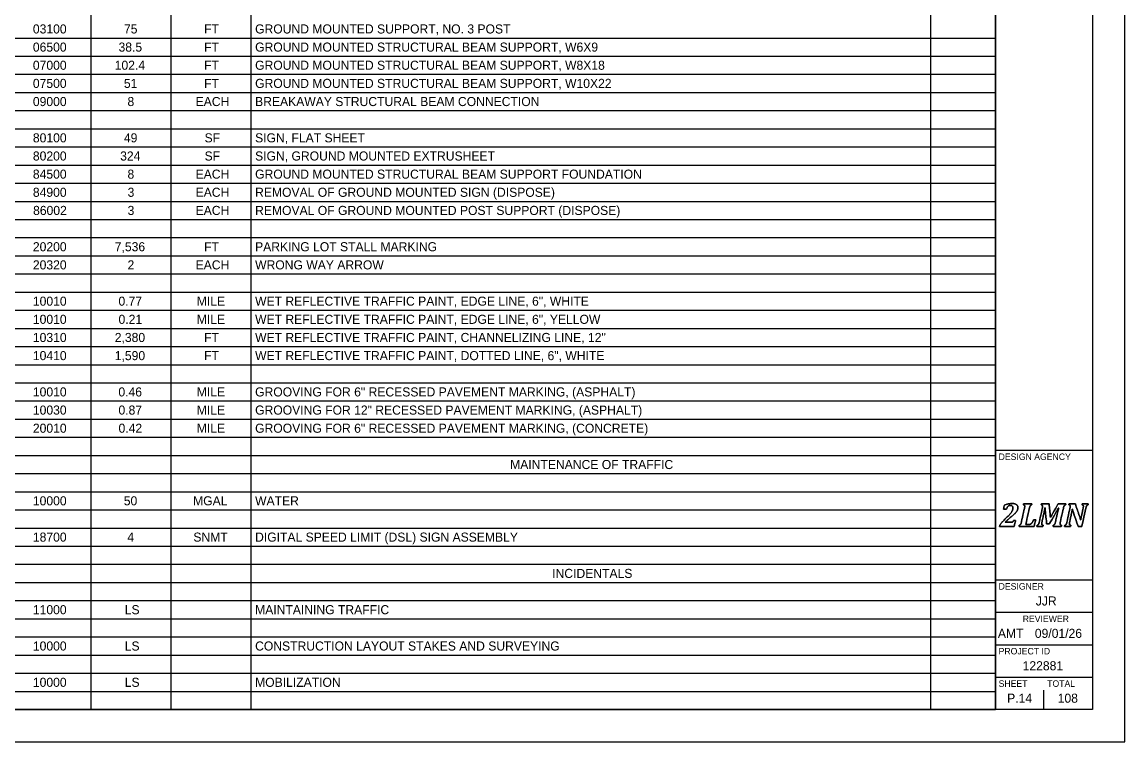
# Model space of a CAD drawing. Extents: x 0 to 34, y 0 to 22.
# Drawn here: x 16.98 to 34, y 0 to 11.11 of the extents above; entities that cross this region are included whole.
import ezdxf

# ---------------------------------------------------------------- set-up
doc = ezdxf.new("R2010")
doc.units = 0
for name, color, linetype in [('SH_Border', 7, 'Continuous'), ('SH_Cut_Line', 7, 'Continuous'), ('SH_Data', 7, 'Continuous'), ('SH_Text', 7, 'Continuous')]:
    doc.layers.add(name, color=color, linetype=linetype)

msp = doc.modelspace()

# ---------------------------------------------------------------- linework, layer by layer
at = {"layer": 'SH_Border'}
for p, q in [((32, 0.5), (32, 21.5)), ((32, 4.5), (33.5, 4.5)), ((32, 2.5), (33.5, 2.5)), ((32, 2), (33.5, 2)), ((32, 1.5), (33.5, 1.5)), ((32, 1), (33.5, 1))]:
    msp.add_line(p, q, dxfattribs=at)
msp.add_lwpolyline([(1.5, 21.5), (33.5, 21.5), (33.5, 0.5), (1.5, 0.5)], close=True, dxfattribs=at)
at = {"layer": 'SH_Cut_Line'}
msp.add_lwpolyline([(0, 0), (34, 0), (34, 22), (0, 22)], close=True, dxfattribs=at)
at = {"layer": 'SH_Data'}
for p, q in [((32.75, 3.5), (32.75, 3.5)), ((32.75, 0.5), (32.75, 0.8)), ((32.375, 0.675), (32.375, 0.675))]:
    msp.add_line(p, q, dxfattribs=at)
for points in [[(32.237, 3.388), (32.246, 3.388), (32.253, 3.389), (32.258, 3.39), (32.263, 3.392), (32.267, 3.394), (32.27, 3.397), (32.273, 3.401), (32.277, 3.408), (32.281, 3.417), (32.281, 3.417), (32.312, 3.417), (32.312, 3.417), (32.312, 3.417), (32.29, 3.326), (32.29, 3.326), (32.29, 3.326), (32.066, 3.326), (32.066, 3.326), (32.066, 3.326), (32.069, 3.343), (32.069, 3.343), (32.078, 3.358), (32.091, 3.375), (32.106, 3.394), (32.122, 3.412), (32.144, 3.435), (32.172, 3.462), (32.197, 3.486), (32.217, 3.506), (32.23, 3.521), (32.243, 3.537), (32.253, 3.551), (32.259, 3.566), (32.266, 3.58), (32.269, 3.595), (32.269, 3.61), (32.269, 3.622), (32.266, 3.632), (32.26, 3.64), (32.253, 3.647), (32.245, 3.65), (32.234, 3.65), (32.22, 3.65), (32.208, 3.646), (32.198, 3.636), (32.188, 3.627), (32.18, 3.613), (32.172, 3.593), (32.172, 3.593), (32.126, 3.593), (32.126, 3.593), (32.126, 3.593), (32.14, 3.654), (32.14, 3.654), (32.166, 3.663), (32.188, 3.669), (32.205, 3.673), (32.223, 3.676), (32.24, 3.678), (32.258, 3.678), (32.278, 3.678), (32.295, 3.675), (32.309, 3.669), (32.322, 3.664), (32.332, 3.656), (32.339, 3.646), (32.345, 3.637), (32.348, 3.626), (32.348, 3.613), (32.348, 3.602), (32.346, 3.591), (32.342, 3.581), (32.339, 3.571), (32.333, 3.56), (32.324, 3.549), (32.315, 3.539), (32.304, 3.526), (32.289, 3.513), (32.275, 3.499), (32.254, 3.482), (32.228, 3.46), (32.216, 3.45), (32.202, 3.438), (32.188, 3.425), (32.174, 3.412), (32.162, 3.4), (32.154, 3.391), (32.154, 3.391), (32.153, 3.388), (32.153, 3.388), (32.153, 3.388), (32.237, 3.388), (32.237, 3.388)], [(32.237, 3.388), (32.237, 3.388), (32.153, 3.388), (32.153, 3.388), (32.153, 3.388), (32.154, 3.391), (32.154, 3.391), (32.162, 3.4), (32.174, 3.412), (32.188, 3.425), (32.202, 3.438), (32.216, 3.45), (32.228, 3.46), (32.254, 3.482), (32.275, 3.499), (32.289, 3.513), (32.304, 3.526), (32.315, 3.539), (32.324, 3.549), (32.333, 3.56), (32.339, 3.571), (32.342, 3.581), (32.346, 3.591), (32.348, 3.602), (32.348, 3.613), (32.348, 3.626), (32.345, 3.637), (32.339, 3.646), (32.332, 3.656), (32.322, 3.664), (32.309, 3.669), (32.295, 3.675), (32.278, 3.678), (32.258, 3.678), (32.24, 3.678), (32.223, 3.676), (32.205, 3.673), (32.188, 3.669), (32.166, 3.663), (32.14, 3.654), (32.14, 3.654), (32.126, 3.593), (32.126, 3.593), (32.126, 3.593), (32.172, 3.593), (32.172, 3.593), (32.18, 3.613), (32.188, 3.627), (32.198, 3.636), (32.208, 3.646), (32.22, 3.65), (32.234, 3.65), (32.245, 3.65), (32.253, 3.647), (32.26, 3.64), (32.266, 3.632), (32.269, 3.622), (32.269, 3.61), (32.269, 3.595), (32.266, 3.58), (32.259, 3.566), (32.253, 3.551), (32.243, 3.537), (32.23, 3.521), (32.217, 3.506), (32.197, 3.486), (32.172, 3.462), (32.144, 3.435), (32.122, 3.412), (32.106, 3.394), (32.091, 3.375), (32.078, 3.358), (32.069, 3.343), (32.069, 3.343), (32.066, 3.326), (32.066, 3.326), (32.066, 3.326), (32.29, 3.326), (32.29, 3.326), (32.29, 3.326), (32.312, 3.417), (32.312, 3.417), (32.312, 3.417), (32.281, 3.417), (32.281, 3.417), (32.277, 3.408), (32.273, 3.401), (32.27, 3.397), (32.267, 3.394), (32.263, 3.392), (32.258, 3.39), (32.253, 3.389), (32.246, 3.388), (32.237, 3.388)], [(32.518, 3.356), (32.527, 3.356), (32.533, 3.357), (32.538, 3.358), (32.542, 3.36), (32.546, 3.362), (32.55, 3.365), (32.554, 3.368), (32.558, 3.372), (32.562, 3.377), (32.567, 3.382), (32.571, 3.388), (32.576, 3.397), (32.58, 3.405), (32.585, 3.415), (32.589, 3.427), (32.589, 3.427), (32.624, 3.427), (32.624, 3.427), (32.624, 3.427), (32.598, 3.326), (32.598, 3.326), (32.598, 3.326), (32.365, 3.326), (32.365, 3.326), (32.365, 3.326), (32.369, 3.343), (32.369, 3.343), (32.376, 3.345), (32.381, 3.348), (32.385, 3.351), (32.389, 3.355), (32.392, 3.36), (32.395, 3.366), (32.398, 3.373), (32.4, 3.382), (32.403, 3.395), (32.403, 3.395), (32.449, 3.605), (32.449, 3.605), (32.452, 3.615), (32.453, 3.625), (32.453, 3.635), (32.453, 3.642), (32.451, 3.647), (32.448, 3.651), (32.444, 3.654), (32.439, 3.656), (32.432, 3.657), (32.432, 3.657), (32.435, 3.674), (32.435, 3.674), (32.435, 3.674), (32.563, 3.674), (32.563, 3.674), (32.563, 3.674), (32.559, 3.657), (32.559, 3.657), (32.552, 3.655), (32.547, 3.652), (32.543, 3.649), (32.539, 3.645), (32.536, 3.64), (32.533, 3.634), (32.531, 3.627), (32.528, 3.618), (32.525, 3.605), (32.525, 3.605), (32.47, 3.356), (32.47, 3.356), (32.47, 3.356), (32.518, 3.356), (32.518, 3.356)], [(32.518, 3.356), (32.518, 3.356), (32.47, 3.356), (32.47, 3.356), (32.47, 3.356), (32.525, 3.605), (32.525, 3.605), (32.528, 3.618), (32.531, 3.627), (32.533, 3.634), (32.536, 3.64), (32.539, 3.645), (32.543, 3.649), (32.547, 3.652), (32.552, 3.655), (32.559, 3.657), (32.559, 3.657), (32.563, 3.674), (32.563, 3.674), (32.563, 3.674), (32.435, 3.674), (32.435, 3.674), (32.435, 3.674), (32.432, 3.657), (32.432, 3.657), (32.439, 3.656), (32.444, 3.654), (32.448, 3.651), (32.451, 3.647), (32.453, 3.642), (32.453, 3.635), (32.453, 3.625), (32.452, 3.615), (32.449, 3.605), (32.449, 3.605), (32.403, 3.395), (32.403, 3.395), (32.4, 3.382), (32.398, 3.373), (32.395, 3.366), (32.392, 3.36), (32.389, 3.355), (32.385, 3.351), (32.381, 3.348), (32.376, 3.345), (32.369, 3.343), (32.369, 3.343), (32.365, 3.326), (32.365, 3.326), (32.365, 3.326), (32.598, 3.326), (32.598, 3.326), (32.598, 3.326), (32.624, 3.427), (32.624, 3.427), (32.624, 3.427), (32.589, 3.427), (32.589, 3.427), (32.585, 3.415), (32.58, 3.405), (32.576, 3.397), (32.571, 3.388), (32.567, 3.382), (32.562, 3.377), (32.558, 3.372), (32.554, 3.368), (32.55, 3.365), (32.546, 3.362), (32.542, 3.36), (32.538, 3.358), (32.533, 3.357), (32.527, 3.356), (32.518, 3.356)], [(32.829, 3.674), (32.829, 3.674), (32.849, 3.461), (32.849, 3.461), (32.849, 3.461), (32.969, 3.674), (32.969, 3.674), (32.969, 3.674), (33.087, 3.674), (33.087, 3.674), (33.087, 3.674), (33.084, 3.657), (33.084, 3.657), (33.077, 3.655), (33.071, 3.652), (33.067, 3.649), (33.064, 3.645), (33.06, 3.64), (33.058, 3.634), (33.055, 3.627), (33.052, 3.618), (33.05, 3.605), (33.05, 3.605), (33.003, 3.395), (33.003, 3.395), (33.002, 3.39), (33.002, 3.387), (33.001, 3.384), (33.001, 3.382), (33.001, 3.379), (33, 3.376), (33, 3.373), (33, 3.369), (33, 3.365), (33, 3.358), (33.002, 3.353), (33.005, 3.349), (33.008, 3.346), (33.014, 3.344), (33.021, 3.343), (33.021, 3.343), (33.018, 3.326), (33.018, 3.326), (33.018, 3.326), (32.89, 3.326), (32.89, 3.326), (32.89, 3.326), (32.893, 3.343), (32.893, 3.343), (32.9, 3.345), (32.906, 3.348), (32.91, 3.351), (32.914, 3.355), (32.917, 3.36), (32.919, 3.366), (32.922, 3.373), (32.925, 3.382), (32.928, 3.395), (32.928, 3.395), (32.951, 3.502), (32.951, 3.502), (32.954, 3.513), (32.957, 3.529), (32.962, 3.548), (32.967, 3.568), (32.972, 3.588), (32.978, 3.609), (32.978, 3.609), (32.973, 3.609), (32.973, 3.609), (32.965, 3.594), (32.957, 3.579), (32.948, 3.563), (32.948, 3.563), (32.833, 3.364), (32.833, 3.364), (32.833, 3.364), (32.792, 3.364), (32.792, 3.364), (32.792, 3.364), (32.775, 3.518), (32.775, 3.518), (32.773, 3.537), (32.772, 3.554), (32.77, 3.569), (32.769, 3.583), (32.768, 3.597), (32.768, 3.611), (32.768, 3.611), (32.764, 3.611), (32.764, 3.611), (32.761, 3.596), (32.758, 3.578), (32.755, 3.558), (32.751, 3.538), (32.747, 3.521), (32.744, 3.507), (32.744, 3.507), (32.72, 3.395), (32.72, 3.395), (32.719, 3.39), (32.718, 3.387), (32.718, 3.384), (32.717, 3.382), (32.717, 3.379), (32.717, 3.376), (32.717, 3.373), (32.716, 3.369), (32.716, 3.365), (32.716, 3.358), (32.718, 3.353), (32.721, 3.349), (32.725, 3.346), (32.73, 3.344), (32.738, 3.343), (32.738, 3.343), (32.734, 3.326), (32.734, 3.326), (32.734, 3.326), (32.641, 3.326), (32.641, 3.326), (32.641, 3.326), (32.644, 3.343), (32.644, 3.343), (32.651, 3.345), (32.657, 3.348), (32.661, 3.351), (32.665, 3.355), (32.668, 3.36), (32.67, 3.366), (32.673, 3.373), (32.676, 3.382), (32.679, 3.395), (32.679, 3.395), (32.725, 3.605), (32.725, 3.605), (32.727, 3.615), (32.728, 3.625), (32.728, 3.635), (32.728, 3.642), (32.727, 3.647), (32.723, 3.651), (32.72, 3.654), (32.715, 3.656), (32.707, 3.657), (32.707, 3.657), (32.711, 3.674), (32.711, 3.674), (32.711, 3.674), (32.829, 3.674), (32.829, 3.674)], [(32.829, 3.674), (32.829, 3.674), (32.711, 3.674), (32.711, 3.674), (32.711, 3.674), (32.707, 3.657), (32.707, 3.657), (32.715, 3.656), (32.72, 3.654), (32.723, 3.651), (32.727, 3.647), (32.728, 3.642), (32.728, 3.635), (32.728, 3.625), (32.727, 3.615), (32.725, 3.605), (32.725, 3.605), (32.679, 3.395), (32.679, 3.395), (32.676, 3.382), (32.673, 3.373), (32.67, 3.366), (32.668, 3.36), (32.665, 3.355), (32.661, 3.351), (32.657, 3.348), (32.651, 3.345), (32.644, 3.343), (32.644, 3.343), (32.641, 3.326), (32.641, 3.326), (32.641, 3.326), (32.734, 3.326), (32.734, 3.326), (32.734, 3.326), (32.738, 3.343), (32.738, 3.343), (32.73, 3.344), (32.725, 3.346), (32.721, 3.349), (32.718, 3.353), (32.716, 3.358), (32.716, 3.365), (32.716, 3.369), (32.717, 3.373), (32.717, 3.376), (32.717, 3.379), (32.717, 3.382), (32.718, 3.384), (32.718, 3.387), (32.719, 3.39), (32.72, 3.395), (32.72, 3.395), (32.744, 3.507), (32.744, 3.507), (32.747, 3.521), (32.751, 3.538), (32.755, 3.558), (32.758, 3.578), (32.761, 3.596), (32.764, 3.611), (32.764, 3.611), (32.768, 3.611), (32.768, 3.611), (32.768, 3.597), (32.769, 3.583), (32.77, 3.569), (32.772, 3.554), (32.773, 3.537), (32.775, 3.518), (32.775, 3.518), (32.792, 3.364), (32.792, 3.364), (32.792, 3.364), (32.833, 3.364), (32.833, 3.364), (32.833, 3.364), (32.948, 3.563), (32.948, 3.563), (32.957, 3.579), (32.965, 3.594), (32.973, 3.609), (32.973, 3.609), (32.978, 3.609), (32.978, 3.609), (32.972, 3.588), (32.967, 3.568), (32.962, 3.548), (32.957, 3.529), (32.954, 3.513), (32.951, 3.502), (32.951, 3.502), (32.928, 3.395), (32.928, 3.395), (32.925, 3.382), (32.922, 3.373), (32.919, 3.366), (32.917, 3.36), (32.914, 3.355), (32.91, 3.351), (32.906, 3.348), (32.9, 3.345), (32.893, 3.343), (32.893, 3.343), (32.89, 3.326), (32.89, 3.326), (32.89, 3.326), (33.018, 3.326), (33.018, 3.326), (33.018, 3.326), (33.021, 3.343), (33.021, 3.343), (33.014, 3.344), (33.008, 3.346), (33.005, 3.349), (33.002, 3.353), (33, 3.358), (33, 3.365), (33, 3.369), (33, 3.373), (33, 3.376), (33.001, 3.379), (33.001, 3.382), (33.001, 3.384), (33.002, 3.387), (33.002, 3.39), (33.003, 3.395), (33.003, 3.395), (33.05, 3.605), (33.05, 3.605), (33.052, 3.618), (33.055, 3.627), (33.058, 3.634), (33.06, 3.64), (33.064, 3.645), (33.067, 3.649), (33.071, 3.652), (33.077, 3.655), (33.084, 3.657), (33.084, 3.657), (33.087, 3.674), (33.087, 3.674), (33.087, 3.674), (32.969, 3.674), (32.969, 3.674), (32.969, 3.674), (32.849, 3.461), (32.849, 3.461), (32.849, 3.461), (32.829, 3.674), (32.829, 3.674)], [(33.137, 3.674), (33.137, 3.674), (33.234, 3.674), (33.234, 3.674), (33.234, 3.674), (33.283, 3.53), (33.283, 3.53), (33.296, 3.49), (33.307, 3.456), (33.315, 3.426), (33.315, 3.426), (33.318, 3.426), (33.318, 3.426), (33.323, 3.455), (33.329, 3.488), (33.337, 3.523), (33.337, 3.523), (33.355, 3.605), (33.355, 3.605), (33.357, 3.615), (33.358, 3.625), (33.358, 3.635), (33.358, 3.642), (33.357, 3.647), (33.353, 3.651), (33.35, 3.654), (33.345, 3.656), (33.337, 3.657), (33.337, 3.657), (33.341, 3.674), (33.341, 3.674), (33.341, 3.674), (33.434, 3.674), (33.434, 3.674), (33.434, 3.674), (33.431, 3.657), (33.431, 3.657), (33.424, 3.655), (33.418, 3.652), (33.414, 3.649), (33.41, 3.645), (33.407, 3.64), (33.405, 3.634), (33.402, 3.627), (33.399, 3.618), (33.396, 3.605), (33.396, 3.605), (33.335, 3.326), (33.335, 3.326), (33.335, 3.326), (33.277, 3.326), (33.277, 3.326), (33.277, 3.326), (33.216, 3.504), (33.216, 3.504), (33.211, 3.518), (33.207, 3.531), (33.204, 3.543), (33.2, 3.556), (33.195, 3.571), (33.19, 3.59), (33.19, 3.59), (33.186, 3.59), (33.186, 3.59), (33.185, 3.579), (33.182, 3.563), (33.179, 3.543), (33.175, 3.523), (33.17, 3.501), (33.165, 3.478), (33.165, 3.478), (33.147, 3.395), (33.147, 3.395), (33.146, 3.39), (33.145, 3.387), (33.145, 3.384), (33.144, 3.382), (33.144, 3.379), (33.144, 3.376), (33.143, 3.373), (33.143, 3.369), (33.143, 3.365), (33.143, 3.358), (33.145, 3.353), (33.148, 3.349), (33.152, 3.346), (33.157, 3.344), (33.164, 3.343), (33.164, 3.343), (33.161, 3.326), (33.161, 3.326), (33.161, 3.326), (33.067, 3.326), (33.067, 3.326), (33.067, 3.326), (33.071, 3.343), (33.071, 3.343), (33.078, 3.345), (33.083, 3.348), (33.087, 3.351), (33.091, 3.355), (33.094, 3.36), (33.097, 3.366), (33.1, 3.373), (33.102, 3.382), (33.105, 3.395), (33.105, 3.395), (33.151, 3.605), (33.151, 3.605), (33.154, 3.615), (33.155, 3.625), (33.155, 3.635), (33.155, 3.642), (33.153, 3.647), (33.15, 3.651), (33.146, 3.654), (33.141, 3.656), (33.134, 3.657), (33.134, 3.657), (33.137, 3.674), (33.137, 3.674)], [(33.137, 3.674), (33.137, 3.674), (33.134, 3.657), (33.134, 3.657), (33.141, 3.656), (33.146, 3.654), (33.15, 3.651), (33.153, 3.647), (33.155, 3.642), (33.155, 3.635), (33.155, 3.625), (33.154, 3.615), (33.151, 3.605), (33.151, 3.605), (33.105, 3.395), (33.105, 3.395), (33.102, 3.382), (33.1, 3.373), (33.097, 3.366), (33.094, 3.36), (33.091, 3.355), (33.087, 3.351), (33.083, 3.348), (33.078, 3.345), (33.071, 3.343), (33.071, 3.343), (33.067, 3.326), (33.067, 3.326), (33.067, 3.326), (33.161, 3.326), (33.161, 3.326), (33.161, 3.326), (33.164, 3.343), (33.164, 3.343), (33.157, 3.344), (33.152, 3.346), (33.148, 3.349), (33.145, 3.353), (33.143, 3.358), (33.143, 3.365), (33.143, 3.369), (33.143, 3.373), (33.144, 3.376), (33.144, 3.379), (33.144, 3.382), (33.145, 3.384), (33.145, 3.387), (33.146, 3.39), (33.147, 3.395), (33.147, 3.395), (33.165, 3.478), (33.165, 3.478), (33.17, 3.501), (33.175, 3.523), (33.179, 3.543), (33.182, 3.563), (33.185, 3.579), (33.186, 3.59), (33.186, 3.59), (33.19, 3.59), (33.19, 3.59), (33.195, 3.571), (33.2, 3.556), (33.204, 3.543), (33.207, 3.531), (33.211, 3.518), (33.216, 3.504), (33.216, 3.504), (33.277, 3.326), (33.277, 3.326), (33.277, 3.326), (33.335, 3.326), (33.335, 3.326), (33.335, 3.326), (33.396, 3.605), (33.396, 3.605), (33.399, 3.618), (33.402, 3.627), (33.405, 3.634), (33.407, 3.64), (33.41, 3.645), (33.414, 3.649), (33.418, 3.652), (33.424, 3.655), (33.431, 3.657), (33.431, 3.657), (33.434, 3.674), (33.434, 3.674), (33.434, 3.674), (33.341, 3.674), (33.341, 3.674), (33.341, 3.674), (33.337, 3.657), (33.337, 3.657), (33.345, 3.656), (33.35, 3.654), (33.353, 3.651), (33.357, 3.647), (33.358, 3.642), (33.358, 3.635), (33.358, 3.625), (33.357, 3.615), (33.355, 3.605), (33.355, 3.605), (33.337, 3.523), (33.337, 3.523), (33.329, 3.488), (33.323, 3.455), (33.318, 3.426), (33.318, 3.426), (33.315, 3.426), (33.315, 3.426), (33.307, 3.456), (33.296, 3.49), (33.283, 3.53), (33.283, 3.53), (33.234, 3.674), (33.234, 3.674), (33.234, 3.674), (33.137, 3.674), (33.137, 3.674)]]:
    msp.add_open_spline(points, degree=3, dxfattribs=at)
at = {"layer": 'SH_Text'}
for p, q in [((18.036, 21.5), (18.036, 0.5)), ((19.272, 21.5), (19.272, 0.5)), ((20.507, 21.5), (20.507, 0.5)), ((30.999, 21.5), (30.999, 0.5)), ((32.004, 21.5), (32.004, 0.5)), ((1.5, 10.86), (32.004, 10.86)), ((1.5, 10.58), (32.004, 10.58)), ((1.5, 10.3), (32.004, 10.3)), ((1.5, 10.02), (32.004, 10.02)), ((1.5, 9.74), (32.004, 9.74)), ((1.5, 9.46), (32.004, 9.46)), ((1.5, 9.18), (32.004, 9.18)), ((1.5, 8.9), (32.004, 8.9)), ((1.5, 8.62), (32.004, 8.62)), ((1.5, 8.34), (32.004, 8.34)), ((1.5, 8.06), (32.004, 8.06)), ((1.5, 7.78), (32.004, 7.78)), ((1.5, 7.5), (32.004, 7.5)), ((1.5, 7.22), (32.004, 7.22)), ((1.5, 6.94), (32.004, 6.94)), ((1.5, 6.66), (32.004, 6.66)), ((1.5, 6.38), (32.004, 6.38)), ((1.5, 6.1), (32.004, 6.1)), ((1.5, 5.82), (32.004, 5.82)), ((1.5, 5.54), (32.004, 5.54)), ((1.5, 5.26), (32.004, 5.26)), ((1.5, 4.98), (32.004, 4.98)), ((1.5, 4.7), (32.004, 4.7)), ((1.5, 4.42), (32.004, 4.42)), ((1.5, 4.14), (32.004, 4.14)), ((1.5, 3.86), (32.004, 3.86)), ((1.5, 3.58), (32.004, 3.58)), ((1.5, 3.3), (32.004, 3.3)), ((1.5, 3.02), (32.004, 3.02)), ((1.5, 2.74), (32.004, 2.74)), ((1.5, 2.46), (32.004, 2.46)), ((1.5, 2.18), (32.004, 2.18)), ((1.5, 1.9), (32.004, 1.9)), ((1.5, 1.62), (32.004, 1.62)), ((1.5, 1.34), (32.004, 1.34)), ((1.5, 1.06), (32.004, 1.06)), ((1.5, 0.78), (32.004, 0.78)), ((1.5, 0.5), (32.004, 0.5))]:
    msp.add_line(p, q, dxfattribs=at)

# ---------------------------------------------------------------- texts
at = {"layer": 'SH_Data'}
for s, height, p in [('DESIGN AGENCY', 0.1, (32.05, 4.35)), ('DESIGNER', 0.1, (32.05, 2.35)), ('JJR', 0.14, (32.624, 2.105)), ('REVIEWER', 0.1, (32.422, 1.85)), ('AMT', 0.14, (32.039, 1.605)), ('09/01/26', 0.14, (32.609, 1.605)), ('PROJECT ID', 0.1, (32.05, 1.35)), ('122881', 0.14, (32.421, 1.105)), ('SHEET', 0.1, (32.05, 0.85)), ('TOTAL', 0.1, (32.8, 0.85)), ('P.14', 0.14, (32.182, 0.605)), ('108', 0.14, (32.962, 0.605))]:
    msp.add_text(s, height=height, dxfattribs=at).set_placement(p)
at = {"layer": 'SH_Text'}
for s, p in [('03100', (17.143, 10.93)), ('75', (18.549, 10.93)), ('FT', (19.786, 10.93)), ('GROUND MOUNTED SUPPORT, NO. 3 POST', (20.573, 10.93)), ('06500', (17.143, 10.65)), ('38.5', (18.465, 10.65)), ('FT', (19.786, 10.65)), ('GROUND MOUNTED STRUCTURAL BEAM SUPPORT, W6X9', (20.573, 10.65)), ('07000', (17.143, 10.37)), ('102.4', (18.406, 10.37)), ('FT', (19.786, 10.37)), ('GROUND MOUNTED STRUCTURAL BEAM SUPPORT, W8X18', (20.573, 10.37)), ('07500', (17.143, 10.09)), ('51', (18.548, 10.09)), ('FT', (19.786, 10.09)), ('GROUND MOUNTED STRUCTURAL BEAM SUPPORT, W10X22', (20.573, 10.09)), ('09000', (17.143, 9.81)), ('8', (18.603, 9.81)), ('EACH', (19.655, 9.81)), ('BREAKAWAY STRUCTURAL BEAM CONNECTION', (20.573, 9.81)), ('80100', (17.143, 9.25)), ('49', (18.548, 9.25)), ('SF', (19.793, 9.25)), ('SIGN, FLAT SHEET', (20.573, 9.25)), ('80200', (17.143, 8.97)), ('324', (18.49, 8.97)), ('SF', (19.793, 8.97)), ('SIGN, GROUND MOUNTED EXTRUSHEET', (20.573, 8.97)), ('84500', (17.143, 8.69)), ('8', (18.603, 8.69)), ('EACH', (19.655, 8.69)), ('GROUND MOUNTED STRUCTURAL BEAM SUPPORT FOUNDATION', (20.573, 8.69)), ('84900', (17.143, 8.41)), ('3', (18.605, 8.41)), ('EACH', (19.655, 8.41)), ('REMOVAL OF GROUND MOUNTED SIGN (DISPOSE)', (20.573, 8.41)), ('86002', (17.146, 8.13)), ('3', (18.605, 8.13)), ('EACH', (19.655, 8.13)), ('REMOVAL OF GROUND MOUNTED POST SUPPORT (DISPOSE)', (20.573, 8.13)), ('20200', (17.143, 7.57)), ('7,536', (18.407, 7.57)), ('FT', (19.786, 7.57)), ('PARKING LOT STALL MARKING', (20.573, 7.57)), ('20320', (17.143, 7.29)), ('2', (18.604, 7.29)), ('EACH', (19.655, 7.29)), ('WRONG WAY ARROW', (20.573, 7.29)), ('10010', (17.143, 6.73)), ('0.77', (18.464, 6.73)), ('MILE', (19.673, 6.73)), ('WET REFLECTIVE TRAFFIC PAINT, EDGE LINE, 6", WHITE', (20.573, 6.73)), ('10010', (17.143, 6.45)), ('0.21', (18.465, 6.45)), ('MILE', (19.673, 6.45)), ('WET REFLECTIVE TRAFFIC PAINT, EDGE LINE, 6", YELLOW', (20.573, 6.45)), ('10310', (17.143, 6.17)), ('2,380', (18.407, 6.17)), ('FT', (19.786, 6.17)), ('WET REFLECTIVE TRAFFIC PAINT, CHANNELIZING LINE, 12"', (20.573, 6.17)), ('10410', (17.143, 5.89)), ('1,590', (18.407, 5.89)), ('FT', (19.786, 5.89)), ('WET REFLECTIVE TRAFFIC PAINT, DOTTED LINE, 6", WHITE', (20.573, 5.89)), ('10010', (17.143, 5.33)), ('0.46', (18.463, 5.33)), ('MILE', (19.673, 5.33)), ('GROOVING FOR 6" RECESSED PAVEMENT MARKING, (ASPHALT)', (20.573, 5.33)), ('10030', (17.143, 5.05)), ('0.87', (18.464, 5.05)), ('MILE', (19.673, 5.05)), ('GROOVING FOR 12" RECESSED PAVEMENT MARKING, (ASPHALT)', (20.573, 5.05)), ('20010', (17.143, 4.77)), ('0.42', (18.465, 4.77)), ('MILE', (19.673, 4.77)), ('GROOVING FOR 6" RECESSED PAVEMENT MARKING, (CONCRETE)', (20.573, 4.77)), ('MAINTENANCE OF TRAFFIC', (24.51, 4.21)), ('10000', (17.143, 3.65)), ('50', (18.546, 3.65)), ('MGAL', (19.616, 3.65)), ('WATER', (20.573, 3.65)), ('DIGITAL SPEED LIMIT (DSL) SIGN ASSEMBLY', (20.573, 3.09)), ('18700', (17.143, 3.09)), ('4', (18.601, 3.09)), ('SNMT', (19.62, 3.09)), ('INCIDENTALS', (25.159, 2.53)), ('11000', (17.143, 1.97)), ('LS', (18.561, 1.97)), ('MAINTAINING TRAFFIC', (20.573, 1.97)), ('10000', (17.143, 1.41)), ('LS', (18.561, 1.41)), ('CONSTRUCTION LAYOUT STAKES AND SURVEYING', (20.573, 1.41)), ('10000', (17.143, 0.85)), ('LS', (18.561, 0.85)), ('MOBILIZATION', (20.573, 0.85))]:
    msp.add_text(s, height=0.14, dxfattribs=at).set_placement(p)

doc.saveas('drawing.dxf')
